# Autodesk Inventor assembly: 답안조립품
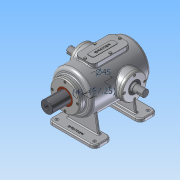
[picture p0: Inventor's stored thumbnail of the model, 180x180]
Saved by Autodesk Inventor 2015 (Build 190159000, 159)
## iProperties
Created: 2016-02
Part Number: 답안조립품
Document SubType Name: Assembly
Designer: Administrator
Mass: 4909.15 g
Surface Area: 4226.6 cm^2
Volume: 1854.17 cm^3
Density: 2.64763 g/cm^3
Author: Administrator
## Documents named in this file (15)
- C:\Users\Administrator\Desktop\360220V1007\답안조립품.iam
- C:\Users\Administrator\Desktop\360220V1007\본체.ipt
- C:\Users\Administrator\Desktop\360220V1007\상부커버.ipt
- C:\Users\Administrator\Desktop\360220V1007\육각머리볼트 M4.ipt
- C:\Users\Administrator\Desktop\360220V1007\축 커버.ipt
- C:\Users\Administrator\Desktop\360220V1007\볼트 M4x0.7.ipt
- C:\Users\Administrator\Desktop\360220V1007\오일실.ipt
- 오일실.ipt
- C:\Users\Administrator\Desktop\360220V1007\슬라이드 커버.ipt
- C:\Users\Administrator\Desktop\360220V1007\부시.ipt
- C:\Users\Administrator\Desktop\360220V1007\베어링 6205.ipt
- 베어링 6205.ipt
- C:\Users\Administrator\Desktop\360220V1007\편심축.ipt
- C:\Users\Administrator\Desktop\360220V1007\가변스프링.ipt
- C:\Users\Administrator\Desktop\360220V1007\슬라이드.ipt
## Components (13 placed, 2 different names)
1. 가변스프링:1
2. M4x0.7:1
3. M4x0.7:2
4. M4x0.7:3
5. M4x0.7:4
6. M4x0.7:5
7. M4x0.7:6
8. M4x0.7:7
9. M4x0.7:8
10. M4x0.7:9
11. M4x0.7:10
12. M4x0.7:11
13. M4x0.7:12
